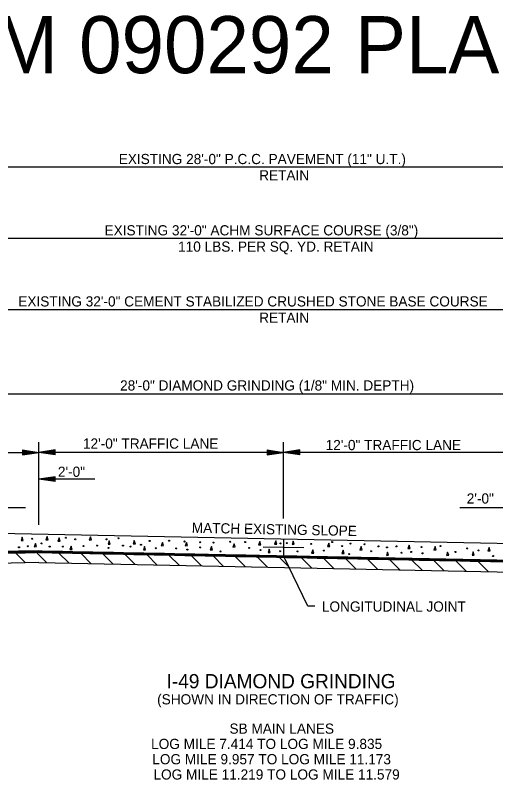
# Model space of a CAD drawing. Extents: x 60325 to 61047, y 53669 to 53767.
# Drawn here: x 60354.1 to 60377.66, y 53678.45 to 53715.97 of the extents above; entities that cross this region are included whole.
import ezdxf

# ---------------------------------------------------------------- set-up
doc = ezdxf.new("R2010")
doc.units = 0
for name, color, linetype in [('Level 63', 7, 'Continuous'), ('R_Border', 7, 'Continuous'), ('R_Border Prem', 7, 'Continuous')]:
    doc.layers.add(name, color=color, linetype=linetype)

msp = doc.modelspace()

# ---------------------------------------------------------------- linework, layer by layer
at = {"layer": 'R_Border'}
for p, q in [((60381.247, 53697.368), (60353.247, 53697.368)), ((60355.247, 53690.957), (60355.247, 53695.015)), ((60367.247, 53691.275), (60367.247, 53695.015)), ((60356.047, 53694.635), (60355.247, 53694.515)), ((60356.047, 53694.395), (60355.247, 53694.515)), ((60367.247, 53694.515), (60355.247, 53694.515)), ((60356.047, 53694.615), (60355.38, 53694.515)), ((60356.047, 53694.415), (60355.38, 53694.515)), ((60356.047, 53694.595), (60355.518, 53694.515)), ((60356.047, 53694.435), (60355.518, 53694.515)), ((60356.047, 53694.575), (60355.651, 53694.515)), ((60356.047, 53694.455), (60355.651, 53694.515)), ((60356.047, 53694.554), (60355.787, 53694.515)), ((60356.047, 53694.476), (60355.787, 53694.515)), ((60356.047, 53694.534), (60355.92, 53694.515)), ((60356.047, 53694.496), (60355.92, 53694.515)), ((60356.047, 53694.395), (60356.047, 53694.635)), ((60366.447, 53694.635), (60367.247, 53694.515)), ((60366.447, 53694.635), (60366.447, 53694.395)), ((60366.447, 53694.615), (60367.113, 53694.515)), ((60366.447, 53694.595), (60366.975, 53694.515)), ((60366.447, 53694.575), (60366.842, 53694.515)), ((60366.447, 53694.554), (60366.707, 53694.515)), ((60366.447, 53694.534), (60366.573, 53694.515)), ((60366.447, 53694.395), (60367.247, 53694.515)), ((60366.447, 53694.476), (60366.707, 53694.515)), ((60366.447, 53694.435), (60366.975, 53694.515)), ((60366.447, 53694.415), (60367.113, 53694.515)), ((60366.447, 53694.455), (60366.842, 53694.515)), ((60366.447, 53694.496), (60366.573, 53694.515)), ((60368.047, 53694.635), (60367.247, 53694.515)), ((60379.247, 53694.515), (60367.247, 53694.515)), ((60368.047, 53694.395), (60367.247, 53694.515)), ((60368.047, 53694.615), (60367.38, 53694.515)), ((60368.047, 53694.415), (60367.38, 53694.515)), ((60368.047, 53694.595), (60367.518, 53694.515)), ((60368.047, 53694.435), (60367.518, 53694.515)), ((60368.047, 53694.575), (60367.651, 53694.515)), ((60368.047, 53694.455), (60367.651, 53694.515)), ((60368.047, 53694.554), (60367.787, 53694.515)), ((60368.047, 53694.476), (60367.787, 53694.515)), ((60368.047, 53694.534), (60367.92, 53694.515)), ((60368.047, 53694.496), (60367.92, 53694.515)), ((60368.047, 53694.395), (60368.047, 53694.635)), ((60356.047, 53693.322), (60355.247, 53693.202)), ((60357.991, 53693.202), (60355.247, 53693.202)), ((60356.047, 53693.082), (60355.247, 53693.202)), ((60356.047, 53693.302), (60355.38, 53693.202)), ((60356.047, 53693.102), (60355.38, 53693.202)), ((60356.047, 53693.282), (60355.518, 53693.202)), ((60356.047, 53693.123), (60355.518, 53693.202)), ((60356.047, 53693.262), (60355.651, 53693.202)), ((60356.047, 53693.143), (60355.651, 53693.202)), ((60356.047, 53693.242), (60355.787, 53693.202)), ((60356.047, 53693.164), (60355.787, 53693.202)), ((60356.047, 53693.221), (60355.92, 53693.202)), ((60356.047, 53693.184), (60355.92, 53693.202)), ((60356.047, 53693.082), (60356.047, 53693.322)), ((60375.9, 53691.809), (60379.247, 53691.809)), ((60353.247, 53690.555), (60381.247, 53689.995)), ((60367.247, 53690.275), (60367.247, 53689.442)), ((60366.247, 53689.878), (60367.247, 53689.858)), ((60367.247, 53689.858), (60368.246, 53689.838)), ((60368.448, 53686.962), (60367.247, 53689.442)), ((60368.795, 53686.962), (60368.448, 53686.962))]:
    msp.add_line(p, q, dxfattribs=at)
at = {"layer": 'R_Border Prem'}
for p, q in [((60381.247, 53708.515), (60353.247, 53708.515)), ((60383.247, 53705.015), (60351.247, 53705.015)), ((60383.247, 53701.515), (60351.247, 53701.515)), ((60347.247, 53694.515), (60355.247, 53694.515)), ((60354.447, 53694.635), (60355.247, 53694.515)), ((60354.447, 53694.635), (60354.447, 53694.395)), ((60354.447, 53694.615), (60355.113, 53694.515)), ((60354.447, 53694.595), (60354.975, 53694.515)), ((60354.447, 53694.575), (60354.842, 53694.515)), ((60354.447, 53694.554), (60354.707, 53694.515)), ((60354.447, 53694.534), (60354.573, 53694.515)), ((60354.447, 53694.395), (60355.247, 53694.515)), ((60354.447, 53694.476), (60354.707, 53694.515)), ((60354.447, 53694.435), (60354.975, 53694.515)), ((60354.447, 53694.415), (60355.113, 53694.515)), ((60354.447, 53694.455), (60354.842, 53694.515)), ((60354.447, 53694.496), (60354.573, 53694.515)), ((60353.247, 53691.809), (60354.589, 53691.809)), ((60355.247, 53689.682), (60351.247, 53689.602)), ((60353.087, 53689.639), (60357.407, 53689.639)), ((60353.587, 53689.649), (60356.907, 53689.649)), ((60354.087, 53689.659), (60356.407, 53689.659)), ((60354.587, 53689.669), (60355.907, 53689.669)), ((60355.087, 53689.679), (60355.407, 53689.679)), ((60355.247, 53689.682), (60383.247, 53689.122)), ((60355.247, 53689.602), (60351.247, 53689.522)), ((60351.247, 53689.599), (60355.088, 53689.599)), ((60351.247, 53689.589), (60354.588, 53689.589)), ((60351.587, 53689.609), (60358.907, 53689.609)), ((60352.087, 53689.619), (60358.407, 53689.619)), ((60352.587, 53689.629), (60357.907, 53689.629)), ((60354.104, 53689.579), (60354.595, 53689.089)), ((60355.144, 53689.6), (60355.65, 53689.094)), ((60355.247, 53689.602), (60383.247, 53689.042)), ((60355.406, 53689.599), (60359.407, 53689.599)), ((60355.906, 53689.589), (60359.907, 53689.589)), ((60356.222, 53689.582), (60356.733, 53689.072)), ((60356.406, 53689.579), (60360.407, 53689.579)), ((60356.906, 53689.569), (60360.907, 53689.569)), ((60357.305, 53689.561), (60357.815, 53689.05)), ((60357.406, 53689.559), (60361.407, 53689.559)), ((60357.906, 53689.549), (60361.907, 53689.549)), ((60358.387, 53689.539), (60358.897, 53689.029)), ((60358.406, 53689.539), (60362.407, 53689.539)), ((60358.906, 53689.529), (60362.907, 53689.529)), ((60359.406, 53689.519), (60363.407, 53689.519)), ((60359.469, 53689.517), (60359.98, 53689.007)), ((60359.906, 53689.509), (60363.907, 53689.509)), ((60360.406, 53689.499), (60364.407, 53689.499)), ((60360.552, 53689.496), (60361.062, 53688.985)), ((60360.906, 53689.489), (60364.907, 53689.489)), ((60361.406, 53689.479), (60365.407, 53689.479)), ((60361.634, 53689.474), (60362.144, 53688.964)), ((60361.906, 53689.469), (60365.907, 53689.469)), ((60362.406, 53689.459), (60366.407, 53689.459)), ((60362.716, 53689.452), (60363.226, 53688.942)), ((60362.906, 53689.449), (60366.907, 53689.449)), ((60363.406, 53689.439), (60367.407, 53689.439)), ((60363.798, 53689.431), (60364.309, 53688.92)), ((60363.906, 53689.429), (60367.907, 53689.429)), ((60364.406, 53689.419), (60368.407, 53689.419)), ((60364.881, 53689.409), (60365.391, 53688.899)), ((60364.906, 53689.409), (60368.907, 53689.409)), ((60365.406, 53689.399), (60369.407, 53689.399)), ((60365.906, 53689.389), (60369.907, 53689.389)), ((60365.963, 53689.387), (60366.473, 53688.877)), ((60366.406, 53689.379), (60370.407, 53689.379)), ((60366.906, 53689.369), (60370.907, 53689.369)), ((60367.045, 53689.366), (60367.556, 53688.855)), ((60367.406, 53689.359), (60371.407, 53689.359)), ((60367.906, 53689.349), (60371.907, 53689.349)), ((60368.128, 53689.344), (60368.638, 53688.834)), ((60368.406, 53689.339), (60372.407, 53689.339)), ((60368.906, 53689.329), (60372.907, 53689.329)), ((60369.21, 53689.322), (60369.72, 53688.812)), ((60369.406, 53689.319), (60373.407, 53689.319)), ((60369.906, 53689.309), (60373.907, 53689.309)), ((60370.292, 53689.301), (60370.803, 53688.791)), ((60370.406, 53689.299), (60374.407, 53689.299)), ((60370.906, 53689.289), (60374.907, 53689.289)), ((60371.375, 53689.279), (60371.885, 53688.769)), ((60371.406, 53689.279), (60375.407, 53689.279)), ((60371.906, 53689.269), (60375.907, 53689.269)), ((60372.406, 53689.259), (60376.407, 53689.259)), ((60372.457, 53689.258), (60372.967, 53688.747)), ((60355.247, 53689.102), (60337.882, 53688.754)), ((60355.247, 53689.102), (60397.793, 53688.251)), ((60372.906, 53689.249), (60376.907, 53689.249)), ((60373.406, 53689.239), (60377.407, 53689.239)), ((60373.539, 53689.236), (60374.049, 53688.726)), ((60373.906, 53689.229), (60377.907, 53689.229)), ((60374.406, 53689.219), (60378.407, 53689.219)), ((60374.621, 53689.214), (60375.132, 53688.704)), ((60374.906, 53689.209), (60378.907, 53689.209)), ((60375.406, 53689.199), (60379.407, 53689.199)), ((60375.704, 53689.193), (60376.214, 53688.682)), ((60375.906, 53689.189), (60379.907, 53689.189)), ((60376.406, 53689.179), (60380.407, 53689.179)), ((60376.786, 53689.171), (60377.296, 53688.661)), ((60376.906, 53689.169), (60380.907, 53689.169)), ((60377.406, 53689.159), (60381.407, 53689.159))]:
    msp.add_line(p, q, dxfattribs=at)
for points in [[(60355.653, 53690.389), (60355.593, 53690.223), (60355.703, 53690.227), (60355.653, 53690.389)], [(60354.438, 53690.348), (60354.378, 53690.182), (60354.488, 53690.187), (60354.438, 53690.348)], [(60355.086, 53690.049), (60355.026, 53689.883), (60355.136, 53689.887), (60355.086, 53690.049)], [(60356.248, 53690.323), (60356.188, 53690.157), (60356.298, 53690.161), (60356.248, 53690.323)], [(60357.781, 53690.376), (60357.721, 53690.21), (60357.831, 53690.214), (60357.781, 53690.376)], [(60358.706, 53690.177), (60358.646, 53690.011), (60358.756, 53690.016), (60358.706, 53690.177)], [(60359.935, 53690.191), (60359.875, 53690.025), (60359.985, 53690.029), (60359.935, 53690.191)], [(60361.31, 53690.098), (60361.249, 53689.932), (60361.359, 53689.937), (60361.31, 53690.098)], [(60362.486, 53690.098), (60362.426, 53689.932), (60362.536, 53689.937), (60362.486, 53690.098)], [(60364.825, 53690.032), (60364.765, 53689.866), (60364.875, 53689.871), (60364.825, 53690.032)], [(60366.094, 53690.138), (60366.033, 53689.972), (60366.143, 53689.976), (60366.094, 53690.138)], [(60366.874, 53690.177), (60366.813, 53690.011), (60366.923, 53690.016), (60366.874, 53690.177)], [(60367.733, 53690.164), (60367.672, 53689.998), (60367.782, 53690.003), (60367.733, 53690.164)], [(60369.477, 53690.059), (60369.417, 53689.893), (60369.527, 53689.897), (60369.477, 53690.059)], [(60356.83, 53689.913), (60356.769, 53689.747), (60356.879, 53689.752), (60356.83, 53689.913)], [(60360.438, 53689.9), (60360.377, 53689.734), (60360.487, 53689.738), (60360.438, 53689.9)], [(60363.715, 53689.9), (60363.655, 53689.734), (60363.765, 53689.738), (60363.715, 53689.9)], [(60366.556, 53689.768), (60366.496, 53689.602), (60366.606, 53689.606), (60366.556, 53689.768)], [(60368.684, 53689.728), (60368.624, 53689.562), (60368.734, 53689.567), (60368.684, 53689.728)], [(60370.178, 53689.715), (60370.117, 53689.549), (60370.227, 53689.553), (60370.178, 53689.715)], [(60371.063, 53689.887), (60371.003, 53689.721), (60371.113, 53689.725), (60371.063, 53689.887)], [(60373.416, 53689.966), (60373.355, 53689.8), (60373.465, 53689.804), (60373.416, 53689.966)], [(60374.684, 53689.887), (60374.624, 53689.721), (60374.734, 53689.725), (60374.684, 53689.887)], [(60376.561, 53689.636), (60376.5, 53689.47), (60376.61, 53689.474), (60376.561, 53689.636)], [(60377.341, 53689.847), (60377.28, 53689.681), (60377.39, 53689.686), (60377.341, 53689.847)], [(60372.358, 53689.622), (60372.298, 53689.456), (60372.408, 53689.461), (60372.358, 53689.622)], [(60375.305, 53689.622), (60375.245, 53689.456), (60375.355, 53689.461), (60375.305, 53689.622)]]:
    msp.add_lwpolyline(points, dxfattribs=at)
for centre in [(60354.925, 53690.275), (60355.386, 53690.048), (60356.576, 53690.325), (60357.038, 53690.246), (60358.571, 53690.246), (60359.153, 53690.299), (60360.686, 53690.167), (60361.637, 53690.18), (60362.391, 53690.14), (60363.17, 53690.101), (60363.818, 53690.087), (60364.637, 53690.127), (60365.377, 53690.114), (60367.109, 53690.048), (60367.413, 53690.061), (60368.615, 53690.021), (60369.646, 53690.114), (60370.545, 53690.035), (60371.232, 53690.008), (60354.277, 53689.853), (60354.714, 53689.91), (60355.783, 53689.889), (60356.43, 53689.889), (60357.448, 53689.916), (60358.109, 53689.942), (60358.664, 53689.823), (60359.378, 53689.942), (60359.748, 53689.889), (60360.263, 53689.982), (60360.99, 53689.81), (60361.994, 53689.797), (60362.536, 53689.744), (60363.17, 53689.849), (60364.162, 53689.651), (60365.563, 53689.823), (60366.118, 53689.717), (60367.082, 53689.664), (60367.941, 53689.651), (60369.237, 53689.691), (60370.135, 53689.916), (60371.549, 53689.664), (60371.906, 53689.902), (60372.329, 53689.849), (60372.792, 53689.902), (60373.518, 53689.625), (60374.021, 53689.863), (60374.959, 53689.916), (60375.686, 53689.625), (60376.267, 53689.797), (60376.822, 53689.704), (60370.479, 53689.519), (60373.043, 53689.585), (60374.074, 53689.559), (60377.536, 53689.427)]:
    msp.add_circle(centre, 0.025, dxfattribs=at)

# ---------------------------------------------------------------- texts
at = {"layer": 'Level 63'}
msp.add_text('FROM 090292 PLANS', height=2.8, dxfattribs=at).set_placement((60345.163, 53713.128))
at = {"layer": 'R_Border'}
for s, height, p in [('28\'-0" DIAMOND GRINDING (1/8" MIN. DEPTH)', 0.5, (60359.237, 53697.551)), ('12\'-0" TRAFFIC LANE', 0.5, (60357.414, 53694.698)), ('12\'-0" TRAFFIC LANE', 0.5, (60369.319, 53694.624)), ('2\'-0"', 0.5, (60356.186, 53693.314)), ('2\'-0"', 0.5, (60376.241, 53692.002)), ('LONGITUDINAL JOINT', 0.5, (60369.136, 53686.697)), ('I-49 DIAMOND GRINDING', 0.7, (60361.516, 53682.934)), ('(SHOWN IN DIRECTION OF TRAFFIC)', 0.5, (60361.054, 53682.143)), ('SB MAIN LANES', 0.5, (60364.602, 53680.704)), ('LOG MILE 7.414 TO LOG MILE 9.835', 0.5, (60360.758, 53679.954)), ('LOG MILE 9.957 TO LOG MILE 11.173', 0.5, (60360.817, 53679.204)), ('LOG MILE 11.219 TO LOG MILE 11.579', 0.5, (60360.874, 53678.454))]:
    msp.add_text(s, height=height, dxfattribs=at).set_placement(p)
msp.add_text('MATCH EXISTING SLOPE', height=0.5, rotation=358.8542, dxfattribs=at).set_placement((60362.748, 53690.569))
at = {"layer": 'R_Border Prem'}
for s, p in [('EXISTING 28\'-0" P.C.C. PAVEMENT (11" U.T.)', (60359.169, 53708.665)), ('RETAIN', (60366.059, 53707.865)), ('EXISTING 32\'-0" ACHM SURFACE COURSE (3/8")', (60358.473, 53705.165)), ('110 LBS. PER SQ. YD. RETAIN', (60362.081, 53704.365)), ('EXISTING 32\'-0" CEMENT STABILIZED CRUSHED STONE BASE COURSE', (60354.243, 53701.676)), ('RETAIN', (60366.059, 53700.876))]:
    msp.add_text(s, height=0.5, dxfattribs=at).set_placement(p)

doc.saveas('drawing.dxf')
